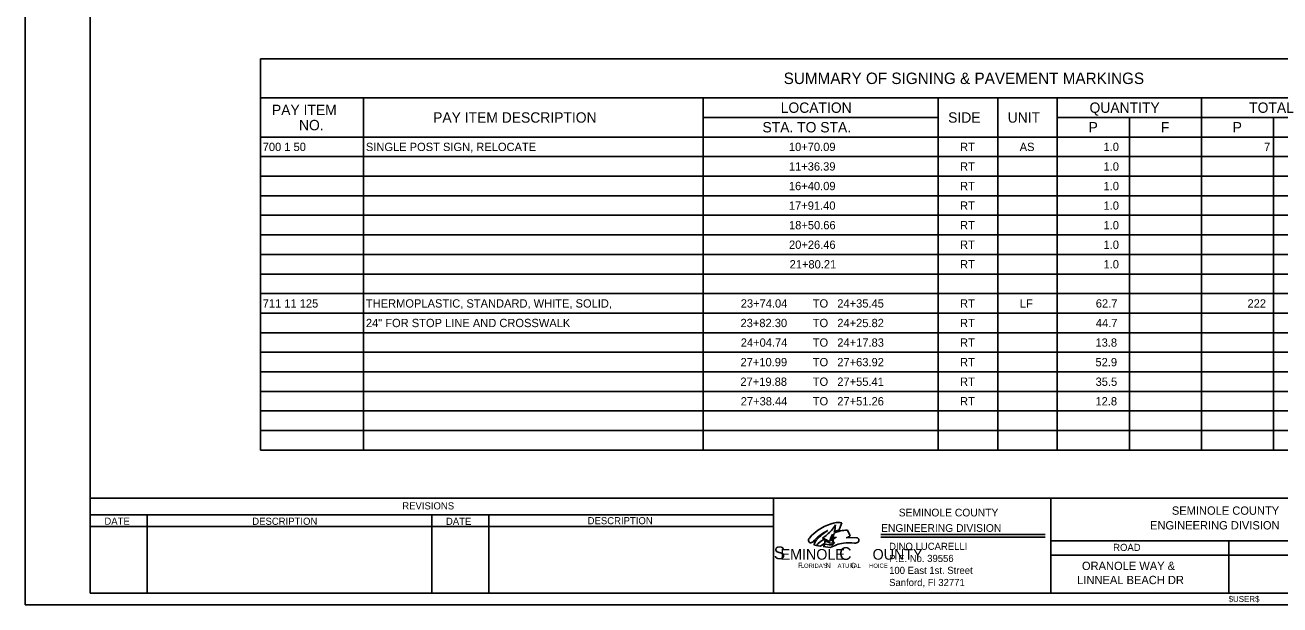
# Model space of a CAD drawing. Extents: x -831.4 to -734.9, y -2212.7 to -2202.1.
# Drawn here: x -751.39 to -740.81, y -2212.74 to -2207.85 of the extents above; entities that cross this region are included whole.
import ezdxf

# ---------------------------------------------------------------- set-up
doc = ezdxf.new("R2010")
doc.units = 0
for name, color, linetype in [('AdhocPoint_dp', 7, 'Continuous'), ('Logo_dp', 7, 'Continuous'), ('PlotBorder_dp', 7, 'Continuous'), ('ScratchEle_dp', 7, 'Continuous'), ('SheetBorder_dp', 7, 'Continuous'), ('SheetLines_dp', 7, 'Continuous'), ('SumBoxBorder_dp', 7, 'Continuous'), ('SumBoxLines_dp', 7, 'Continuous'), ('SumBoxLinesMin_dp', 7, 'Continuous'), ('TextLabel', 7, 'Continuous'), ('TextMinor', 7, 'Continuous'), ('TextMisc', 7, 'Continuous')]:
    doc.layers.add(name, color=color, linetype=linetype)

msp = doc.modelspace()

# ---------------------------------------------------------------- linework, layer by layer
at = {"layer": 'AdhocPoint_dp'}
msp.add_line((-751.391, -2212.74), (-751.391, -2212.74), dxfattribs=at)
at = {"layer": 'Logo_dp'}
for p, q in [((-744.53, -2212.112), (-744.505, -2212.048)), ((-744.433, -2212.157), (-744.457, -2212.111)), ((-744.718, -2212.238), (-744.684, -2212.244)), ((-744.684, -2212.244), (-744.647, -2212.22)), ((-744.661, -2212.249), (-744.601, -2212.257)), ((-744.647, -2212.22), (-744.647, -2212.205)), ((-744.63, -2212.209), (-744.616, -2212.2)), ((-744.566, -2212.212), (-744.579, -2212.232)), ((-744.377, -2212.175), (-744.466, -2212.173))]:
    msp.add_line(p, q, dxfattribs=at)
for points in [[(-744.564, -2212.047), (-744.564, -2212.047)], [(-744.712, -2212.187), (-744.712, -2212.187)]]:
    msp.add_lwpolyline(points, dxfattribs=at)
for centre, radius, start, end in [((-744.475, -2212.434), 0.397, 102.9903, 139.6059), ((-744.536, -2212.168), 0.124, 75.3253, 102.9903), ((-744.47, -2212.443), 0.363, 114.9659, 139.5324), ((-744.37, -2212.511), 0.471, 122.4911, 136.5671), ((-744.962, -2211.749), 0.52, 304.6341, 315.4846), ((-744.433, -2212.231), 0.173, 149.8559, 166.6084), ((-744.717, -2211.99), 0.176, 315.4846, 334.5843), ((-744.482, -2212.172), 0.104, 164.7271, 186.2913), ((-744.261, -2212.199), 0.315, 168.5397, 176.4368), ((-744.462, -2212.354), 0.243, 88.8097, 116.3253), ((-744.782, -2212.06), 0.224, 343.2724, 358.4983), ((-744.49, -2212.291), 0.184, 102.6743, 114.927), ((-744.754, -2212.196), 0.0305, 139.6059, 196.4516), ((-744.769, -2212.201), 0.015, 196.4516, 259.2243), ((-744.767, -2212.188), 0.0281, 259.2243, 316.3038), ((-744.628, -2212.267), 0.116, 136.5671, 163.5792), ((-744.817, -2212.7), 0.472, 77.906, 80.5112), ((-744.539, -2212.396), 0.238, 117.2749, 138.5612), ((-744.539, -2212.396), 0.238, 117.2749, 138.5612), ((-744.693, -2212.272), 0.0982, 63.4009, 74.6531), ((-744.388, -2212.468), 0.35, 136.6419, 141.2542), ((-744.662, -2212.208), 0.0152, 9.3089, 39.4038), ((-744.657, -2212.226), 0.0288, 52.8844, 76.2699), ((-744.8, -2212.526), 0.374, 60.5981, 66.1485), ((-744.596, -2212.031), 0.202, 256.604, 274.8219), ((-744.61, -2212.165), 0.0482, 231.8585, 245.4301), ((-744.252, -2212.754), 0.656, 120.5054, 124.3665), ((-744.594, -2212.159), 0.0603, 242.5498, 297.6527), ((-744.448, -2212.477), 0.324, 115.0847, 118.1751), ((-744.419, -2212.604), 0.392, 100.5294, 117.6775), ((-744.547, -2212.184), 0.0385, 187.6078, 223.6575), ((-744.252, -2212.754), 0.656, 117.0216, 119.5789), ((-744.261, -2212.199), 0.315, 177.2074, 179.7242), ((-744.533, -2212.199), 0.0427, 177.7479, 195.3391), ((-744.448, -2212.477), 0.324, 108.2919, 113.1245), ((-744.443, -2212.743), 0.526, 84.8254, 95.1746), ((-744.501, -2212.057), 0.122, 286.9862, 304.2368), ((-744.391, -2212.181), 0.0383, 262.9671, 309.9257), ((-744.376, -2212.191), 0.0161, 0.9885, 92.5741), ((-744.387, -2212.193), 0.0268, 319.3898, 5.6197)]:
    msp.add_arc(centre, radius, start, end, dxfattribs=at)
at = {"layer": 'PlotBorder_dp'}
msp.add_lwpolyline([(-751.391, -2212.74), (-734.891, -2212.74), (-734.891, -2202.14), (-751.391, -2202.14)], close=True, dxfattribs=at)
at = {"layer": 'SheetBorder_dp'}
for p, q in [((-750.841, -2202.24), (-750.841, -2212.64)), ((-750.841, -2211.84), (-735.441, -2211.84)), ((-750.841, -2212.64), (-735.441, -2212.64))]:
    msp.add_line(p, q, dxfattribs=at)
at = {"layer": 'SheetLines_dp'}
for p, q in [((-745.081, -2211.84), (-745.081, -2212.64)), ((-742.741, -2211.84), (-742.741, -2212.64)), ((-750.841, -2211.98), (-745.081, -2211.98)), ((-750.361, -2211.98), (-750.361, -2212.64)), ((-747.961, -2211.98), (-747.961, -2212.64)), ((-747.481, -2211.98), (-747.481, -2212.64)), ((-750.841, -2212.08), (-745.081, -2212.08)), ((-742.741, -2212.2), (-739.741, -2212.2)), ((-741.241, -2212.2), (-741.241, -2212.64)), ((-742.741, -2212.32), (-739.741, -2212.32))]:
    msp.add_line(p, q, dxfattribs=at)
at = {"layer": 'SumBoxBorder_dp'}
for p, q in [((-749.407, -2208.135), (-737.047, -2208.135)), ((-749.407, -2208.135), (-749.407, -2211.435)), ((-749.407, -2211.435), (-737.047, -2211.435))]:
    msp.add_line(p, q, dxfattribs=at)
at = {"layer": 'SumBoxLines_dp'}
for p, q in [((-749.407, -2208.465), (-737.047, -2208.465)), ((-749.407, -2208.465), (-737.047, -2208.465)), ((-748.537, -2208.465), (-748.537, -2211.435)), ((-748.537, -2208.465), (-748.537, -2211.435)), ((-745.672, -2208.465), (-745.672, -2211.435)), ((-745.672, -2208.465), (-745.672, -2211.435)), ((-743.692, -2208.465), (-743.692, -2211.435)), ((-743.692, -2208.465), (-743.692, -2211.435)), ((-743.189, -2208.465), (-743.189, -2211.435)), ((-743.189, -2208.465), (-743.189, -2211.435)), ((-742.687, -2208.465), (-742.687, -2211.435)), ((-742.687, -2208.465), (-742.687, -2211.435)), ((-741.472, -2208.465), (-741.472, -2208.795)), ((-741.472, -2208.465), (-741.472, -2211.435)), ((-745.672, -2208.63), (-743.692, -2208.63)), ((-745.672, -2208.63), (-743.692, -2208.63)), ((-742.687, -2208.63), (-741.472, -2208.63)), ((-742.687, -2208.63), (-740.257, -2208.63)), ((-749.407, -2208.795), (-737.047, -2208.795))]:
    msp.add_line(p, q, dxfattribs=at)
at = {"layer": 'SumBoxLinesMin_dp'}
for p, q in [((-742.079, -2208.63), (-742.079, -2211.435)), ((-742.079, -2208.63), (-742.079, -2211.435)), ((-740.864, -2208.63), (-740.864, -2211.435)), ((-740.864, -2208.63), (-740.864, -2211.435)), ((-749.407, -2208.96), (-737.047, -2208.96)), ((-749.407, -2208.96), (-737.047, -2208.96)), ((-749.407, -2209.125), (-737.047, -2209.125)), ((-749.407, -2209.125), (-737.047, -2209.125)), ((-749.407, -2209.29), (-737.047, -2209.29)), ((-749.407, -2209.29), (-737.047, -2209.29)), ((-749.407, -2209.455), (-737.047, -2209.455)), ((-749.407, -2209.455), (-737.047, -2209.455)), ((-749.407, -2209.62), (-737.047, -2209.62)), ((-749.407, -2209.62), (-737.047, -2209.62)), ((-749.407, -2209.785), (-737.047, -2209.785)), ((-749.407, -2209.785), (-737.047, -2209.785)), ((-749.407, -2209.95), (-737.047, -2209.95)), ((-749.407, -2209.95), (-737.047, -2209.95)), ((-749.407, -2210.115), (-737.047, -2210.115)), ((-749.407, -2210.115), (-737.047, -2210.115)), ((-749.407, -2210.28), (-737.047, -2210.28)), ((-749.407, -2210.28), (-737.047, -2210.28)), ((-749.407, -2210.445), (-737.047, -2210.445)), ((-749.407, -2210.445), (-737.047, -2210.445)), ((-749.407, -2210.61), (-737.047, -2210.61)), ((-749.407, -2210.61), (-737.047, -2210.61)), ((-749.407, -2210.775), (-737.047, -2210.775)), ((-749.407, -2210.775), (-737.047, -2210.775)), ((-749.407, -2210.94), (-737.047, -2210.94)), ((-749.407, -2210.94), (-737.047, -2210.94)), ((-749.407, -2211.105), (-737.047, -2211.105)), ((-749.407, -2211.105), (-737.047, -2211.105)), ((-749.407, -2211.27), (-737.047, -2211.27)), ((-749.407, -2211.27), (-737.047, -2211.27))]:
    msp.add_line(p, q, dxfattribs=at)
at = {"layer": 'TextMisc'}
for p, q in [((-744.175, -2212.146), (-742.788, -2212.146)), ((-744.176, -2212.168), (-742.79, -2212.168))]:
    msp.add_line(p, q, dxfattribs=at)

# ---------------------------------------------------------------- texts
at = {"layer": 'Logo_dp'}
for s, height, p in [('S', 0.108, (-745.078, -2212.355)), ('C', 0.108, (-744.526, -2212.361)), ('EMINOLE       OUNTY', 0.09, (-745.02, -2212.359)), ('F', 0.045, (-744.874, -2212.43)), ("LORIDA'S      ATURAL     HOICE", 0.036, (-744.85, -2212.428)), ('N', 0.045, (-744.64, -2212.43)), ('C', 0.045, (-744.431, -2212.43))]:
    msp.add_text(s, height=height, dxfattribs=at).set_placement(p)
at = {"layer": 'ScratchEle_dp'}
for s, p in [('Sheet: 1', (-750.841, -2211.838)), ('Angle:  90.0153', (-750.841, -2211.842)), ('Align: CH269', (-750.841, -2211.846))]:
    msp.add_text(s, height=0.00295, dxfattribs=at).set_placement(p)
at = {"layer": 'TextLabel'}
for s, height, p in [('SUMMARY OF SIGNING & PAVEMENT MARKINGS', 0.09625, (-744.994, -2208.348)), ('PAY ITEM', 0.0875, (-749.309, -2208.61)), ('LOCATION', 0.0875, (-745.019, -2208.591)), ('QUANTITY', 0.0875, (-742.415, -2208.591)), ('TOTAL', 0.0875, (-741.069, -2208.591)), ('NO.', 0.0875, (-749.081, -2208.738)), ('PAY ITEM DESCRIPTION', 0.0875, (-747.95, -2208.674)), ('SIDE', 0.0875, (-743.607, -2208.674)), ('UNIT', 0.0875, (-743.105, -2208.674)), ('STA. TO STA.', 0.0875, (-745.173, -2208.756)), ('P', 0.0875, (-742.423, -2208.756)), ('F', 0.0875, (-741.814, -2208.756)), ('P', 0.0875, (-741.208, -2208.756)), ('700 1 50', 0.07, (-749.387, -2208.913)), ('SINGLE POST SIGN, RELOCATE', 0.07, (-748.517, -2208.913)), ('10+70.09', 0.07, (-744.95, -2208.913)), ('RT', 0.07, (-743.507, -2208.913)), ('AS', 0.07, (-743.004, -2208.913)), ('1.0', 0.07, (-742.297, -2208.913)), ('7', 0.07, (-740.943, -2208.913)), ('11+36.39', 0.07, (-744.95, -2209.078)), ('RT', 0.07, (-743.507, -2209.078)), ('1.0', 0.07, (-742.297, -2209.078)), ('16+40.09', 0.07, (-744.95, -2209.243)), ('RT', 0.07, (-743.507, -2209.243)), ('1.0', 0.07, (-742.297, -2209.243)), ('17+91.40', 0.07, (-744.95, -2209.408)), ('RT', 0.07, (-743.507, -2209.408)), ('1.0', 0.07, (-742.297, -2209.408)), ('18+50.66', 0.07, (-744.949, -2209.573)), ('RT', 0.07, (-743.507, -2209.573)), ('1.0', 0.07, (-742.297, -2209.573)), ('20+26.46', 0.07, (-744.949, -2209.738)), ('RT', 0.07, (-743.507, -2209.738)), ('1.0', 0.07, (-742.297, -2209.738)), ('21+80.21', 0.07, (-744.944, -2209.903)), ('RT', 0.07, (-743.507, -2209.903)), ('1.0', 0.07, (-742.297, -2209.903)), ('711 11 125', 0.07, (-749.387, -2210.233)), ('THERMOPLASTIC, STANDARD, WHITE, SOLID,', 0.07, (-748.517, -2210.233)), ('23+74.04', 0.07, (-745.356, -2210.233)), ('TO', 0.07, (-744.749, -2210.233)), ('24+35.45', 0.07, (-744.542, -2210.233)), ('RT', 0.07, (-743.507, -2210.233)), ('LF', 0.07, (-743.003, -2210.233)), ('62.7', 0.07, (-742.362, -2210.233)), ('222', 0.07, (-741.083, -2210.233)), ('24" FOR STOP LINE AND CROSSWALK', 0.07, (-748.517, -2210.398)), ('23+82.30', 0.07, (-745.358, -2210.398)), ('TO', 0.07, (-744.749, -2210.398)), ('24+25.82', 0.07, (-744.542, -2210.398)), ('RT', 0.07, (-743.507, -2210.398)), ('44.7', 0.07, (-742.362, -2210.398)), ('24+04.74', 0.07, (-745.356, -2210.563)), ('TO', 0.07, (-744.749, -2210.563)), ('24+17.83', 0.07, (-744.542, -2210.563)), ('RT', 0.07, (-743.507, -2210.563)), ('13.8', 0.07, (-742.365, -2210.563)), ('27+10.99', 0.07, (-745.358, -2210.728)), ('TO', 0.07, (-744.749, -2210.728)), ('27+63.92', 0.07, (-744.542, -2210.728)), ('RT', 0.07, (-743.507, -2210.728)), ('52.9', 0.07, (-742.365, -2210.728)), ('27+19.88', 0.07, (-745.359, -2210.893)), ('TO', 0.07, (-744.749, -2210.893)), ('27+55.41', 0.07, (-744.542, -2210.893)), ('RT', 0.07, (-743.507, -2210.893)), ('35.5', 0.07, (-742.364, -2210.893)), ('27+38.44', 0.07, (-745.356, -2211.058)), ('TO', 0.07, (-744.749, -2211.058)), ('27+51.26', 0.07, (-744.542, -2211.058)), ('RT', 0.07, (-743.507, -2211.058)), ('12.8', 0.07, (-742.365, -2211.058))]:
    msp.add_text(s, height=height, dxfattribs=at).set_placement(p)
at = {"layer": 'TextMinor'}
msp.add_text('$USER$', height=0.05, rotation=360, dxfattribs=at).set_placement((-741.242, -2212.715))
at = {"layer": 'TextMisc'}
for s, height, rotation, p in [('REVISIONS', 0.06, 360, (-748.21, -2211.935)), ('SEMINOLE COUNTY', 0.07, 360, (-741.721, -2211.98)), ('DATE', 0.06, 359.8693, (-750.722, -2212.064)), ('DESCRIPTION', 0.06, 0.0498, (-749.475, -2212.065)), ('DATE', 0.06, 359.8693, (-747.842, -2212.065)), ('DESCRIPTION', 0.06, 0.0498, (-746.647, -2212.06)), ('ENGINEERING DIVISION', 0.07, 360, (-741.905, -2212.104)), ('ROAD', 0.06, 360, (-742.216, -2212.285)), ('ORANOLE WAY & ', 0.07, 360, (-742.479, -2212.446)), (' LINNEAL BEACH DR', 0.07, 360, (-742.545, -2212.565))]:
    msp.add_text(s, height=height, rotation=rotation, dxfattribs=at).set_placement(p)
for s, height, p in [('SEMINOLE COUNTY', 0.065, (-744.024, -2211.994)), ('ENGINEERING DIVISION', 0.065, (-744.173, -2212.124)), ('DINO LUCARELLI', 0.06, (-744.105, -2212.276)), ('P.E. No. 39556', 0.06, (-744.105, -2212.378)), ('100 East 1st. Street', 0.06, (-744.105, -2212.479)), ('Sanford, Fl 32771', 0.06, (-744.105, -2212.581))]:
    msp.add_text(s, height=height, dxfattribs=at).set_placement(p)

doc.saveas('drawing.dxf')
